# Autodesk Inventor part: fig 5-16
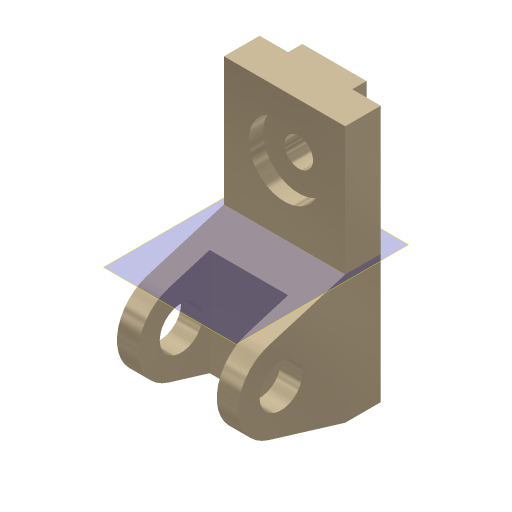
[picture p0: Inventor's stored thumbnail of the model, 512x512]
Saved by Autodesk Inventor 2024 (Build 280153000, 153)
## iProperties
Shininess: 65.0
Angle Display Precision: 2
Document Length Units: 11269
Document Angle Units: 11279
Document Time Units: 11290
Document Mass Units: 11283
Document Length Units Precision: 3
Document Angle Units Precision: 2
Compacted: False
Created: 2001-11
Part Number: fig 5-16
Document SubType Name: Modeling
Designer: Renu Muthoo
Density: 1 g/cm^3
Material: Generic
Appearance: Metal-Titanium (Polished)
Density: 0.0
Volumn: 0.0
Area: 0.0
PropertySet Name: Model Information
Control State: 0
Master: False
Checked Out: False
Author: Renu Muthoo
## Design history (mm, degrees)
sketch "Sketch2"
  geometry: L1 (33.257, 104.664)-(33.257, -75.336); L2 (33.257, -75.336)-(8.257, -75.336); L3 (8.257, -75.336)-(-45.451, -59.045); L4 (-45.451, -1.628)-(8.257, 14.664); L5 (8.257, 14.664)-(8.257, 104.664); L6 (8.257, 104.664)-(33.257, 104.664); C1 r 15 at (-36.743, -30.336); A1 r 30 centre (-36.743, -30.336) between (-45.451, -1.628) and (-45.451, -59.045)
  constraints: 12 end point, 2 centre point, 2 equal length, 2 parallel, 2 point on circle, 2 tangent, 1 coincident, 1 perpendicular, 1 vertical
  dimensions: "d0" = 180 distance of L1.start L1.end; "d1" = 30 radius of A1; "d2" = 25 distance of L5.end L1.start; "d3" = 45 distance from line of L2 A1.centre; "d4" = 70 distance from line of L1 A1.centre; "d5" = 30 diameter of C1
extrude "Extrusion1" new body sketch "Sketch2" distance "d6" = 85; taper "d7" = 0 deg
workplane "Work Plane1"
sketch "Sketch3"
  geometry: L1 (15, 62.364)-(70, 62.364); L2 (70, 62.364)-(70, -52.386); L3 (70, -52.386)-(15, -52.386); L4 (15, -52.386)-(15, 62.364); L5 (0, -45)-(0, -28.708) reference
  constraints: 8 end point, 2 parallel, 1 horizontal, 1 perpendicular
  dimensions: "d8" = 55 distance of L1.start L1.end; "d9" = 15 distance between parallel lines of L5 L4
extrude "Extrusion2" cut sketch "Sketch3" distance "d10" = 50; taper "d11" = 0 deg
sketch "Sketch4"
  geometry: L1 (0, 25)-(85, 25) reference; L2 (0, 0)-(0, 25) reference; L3 (20, 25)-(65, 25); L4 (65, 25)-(65, 35); L5 (65, 35)-(20, 35); L6 (20, 35)-(20, 25)
  constraints: 8 end point, 2 parallel, 1 horizontal, 1 perpendicular, 1 point on line
  dimensions: "d12" = 45 distance of L4.end L5.end; "d13" = 10 distance of L3.end L4.end; "d14" = 20 distance between parallel lines of L2 L6
extrude "Extrusion3" join sketch "Sketch4" stored distance "d15" = 50; taper "d16" = 0 deg
sketch "Sketch5"
  geometry: L1 (85, 0)-(85, 90) reference; L2 (0, 90)-(85, 90) reference; 1 further point
  dimensions: "d17" = 42 distance from line of L2 point (42.5, 48); "d18" = 42.5 distance from line of L1 point (42.5, 48)
hole "Hole1" sketch "Sketch5" diameter "d19" = 20; stored, may be unused: countersink angle "d23" = 82 deg, drill point angle "d25" = 118 deg; dims "d20" = 6, "d21" = 50, "d22" = 10, "d24" = 8
workplane "Work Plane7"
body "Solid1"
node "Sketch1"
other parameters: "d27" = 90 deg
